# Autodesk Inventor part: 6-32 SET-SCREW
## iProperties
Created: 2007-08
Part Number: 6-32 SET-SCREW
Document SubType Name: Modeling
Density: 1 g/cm^3
Mass: 0.0379541 g
Surface Area: 1.01226 cm^2
Volume: 0.0379541 cm^3
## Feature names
1. Base1
